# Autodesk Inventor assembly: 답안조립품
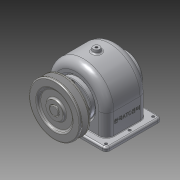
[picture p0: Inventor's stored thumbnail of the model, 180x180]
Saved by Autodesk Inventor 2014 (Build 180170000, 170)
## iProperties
Created: 2015-09
Part Number: 답안조립품
Document SubType Name: Assembly
Designer: USER
Author: USER
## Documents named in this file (14)
- C:\Users\USER\Desktop\450907V1033\답안조립품.iam
- C:\Users\USER\Desktop\450907V1033\본체.ipt
- C:\Users\USER\Desktop\450907V1033\450907V1033\V-벨트풀리.ipt
- C:\Users\USER\Desktop\450907V1033\450907V1033\뒤커버.ipt
- C:\Users\USER\Desktop\450907V1033\450907V1033\멈춤나사 - M4x10.ipt
- C:\Users\USER\Desktop\450907V1033\450907V1033\베어링 6203.ipt
- C:\Users\USER\Desktop\450907V1033\450907V1033\볼트 M3 x 8.ipt
- C:\Users\USER\Desktop\450907V1033\450907V1033\볼트 M3 x 10.ipt
- C:\Users\USER\Desktop\450907V1033\450907V1033\스퍼기어.ipt
- C:\Users\USER\Desktop\450907V1033\450907V1033\앞커버.ipt
- C:\Users\USER\Desktop\450907V1033\450907V1033\오일 실 17 32 8.ipt
- C:\Users\USER\Desktop\450907V1033\450907V1033\축.ipt
- C:\Users\USER\Desktop\450907V1033\450907V1033\키 - 5 x 5 x 18.ipt
- C:\Users\USER\Desktop\450907V1033\450907V1033\키 - 6 x 6 x 22.ipt
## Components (9 placed, 3 different names)
1. V-벨트풀리:1
2. ISO 4762 M3 x 8:1
3. ISO 4762 M3 x 8:2
4. ISO 4762 M3 x 8:3
5. ISO 4762 M3 x 8:4
6. ISO 4762 M3 x 10:1
7. ISO 4762 M3 x 10:2
8. ISO 4762 M3 x 10:3
9. ISO 4762 M3 x 10:4
